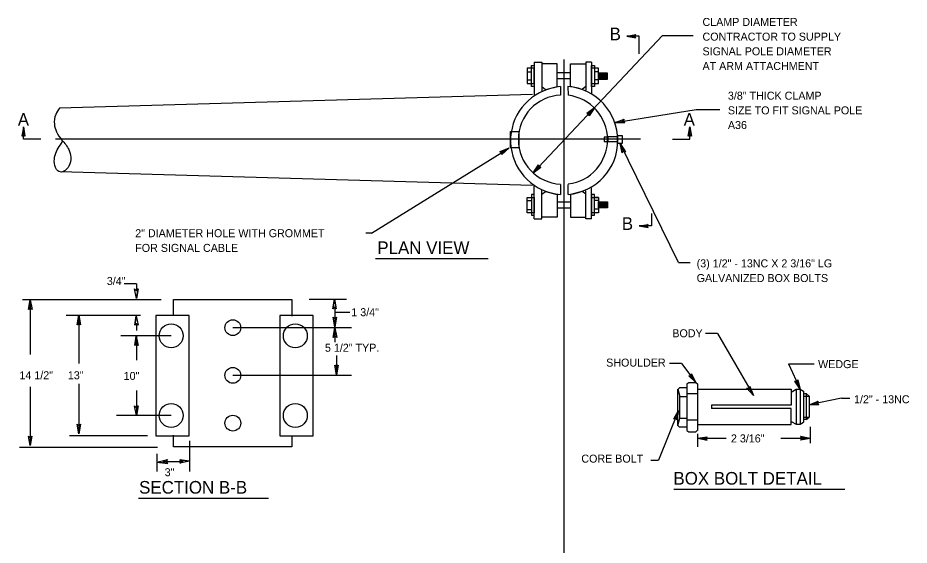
# Model space of a CAD drawing. Extents: x 104.4 to 111.7, y 116.1 to 126.1.
# Drawn here: x 104.4 to 111.45, y 121.98 to 126.14 of the extents above; entities that cross this region are included whole.
import ezdxf

# ---------------------------------------------------------------- set-up
doc = ezdxf.new("R2010")
doc.units = 0
for name, color, linetype in [('DETL-DIMS', 7, 'Continuous'), ('DETL-LINE', 7, 'Continuous'), ('DETL-NOTE', 7, 'Continuous'), ('DETL-TITL', 7, 'Continuous')]:
    doc.layers.add(name, color=color, linetype=linetype)

msp = doc.modelspace()

# ---------------------------------------------------------------- linework, layer by layer
at = {"layer": 'DETL-DIMS'}
for p, q in [((109.2139, 125.9989), (109.2854, 126.0115)), ((109.2719, 125.9989), (109.2854, 126.0115)), ((109.3114, 125.9989), (109.2139, 125.9989)), ((109.2139, 125.9989), (109.2854, 125.9863)), ((109.2854, 125.9863), (109.2719, 125.9989)), ((109.3114, 125.861), (109.3114, 125.9989)), ((108.7182, 120.2988), (108.7182, 125.8152)), ((104.4418, 125.282), (104.4292, 125.2105)), ((104.4418, 125.1845), (104.4418, 125.282)), ((104.4418, 125.282), (104.4544, 125.2105)), ((109.7109, 125.282), (109.6983, 125.2105)), ((109.7109, 125.1845), (109.7109, 125.282)), ((109.7109, 125.282), (109.7235, 125.2105)), ((104.4418, 125.224), (104.4292, 125.2105)), ((104.4544, 125.2105), (104.4418, 125.224)), ((104.5797, 125.1845), (104.4418, 125.1845)), ((109.3219, 125.1845), (104.6962, 125.1845)), ((109.573, 125.1845), (109.7109, 125.1845)), ((109.6983, 125.2105), (109.7109, 125.224)), ((109.7109, 125.224), (109.7235, 125.2105)), ((109.4076, 124.5995), (109.4076, 124.5002)), ((109.3101, 124.5002), (109.3816, 124.5128)), ((109.4076, 124.5002), (109.3101, 124.5002)), ((109.3101, 124.5002), (109.3816, 124.4876)), ((109.3681, 124.5002), (109.3816, 124.5128)), ((109.3816, 124.4876), (109.3681, 124.5002)), ((105.3352, 124.0425), (105.2386, 124.0425)), ((105.3352, 124.0425), (105.3352, 123.9883)), ((105.3353, 123.9271), (105.3218, 124.0025)), ((105.3352, 123.9883), (105.3218, 124.0025)), ((105.3484, 124.0025), (105.3352, 123.9883)), ((105.3353, 123.9271), (105.3484, 124.0025)), ((105.5311, 123.9169), (104.4348, 123.9169)), ((104.4967, 123.9157), (104.4837, 123.8403)), ((104.4967, 123.9157), (104.5103, 123.8403)), ((104.4968, 123.9152), (104.4968, 123.4847)), ((106.9973, 123.9197), (106.7012, 123.9197)), ((106.902, 123.9219), (106.889, 123.8464)), ((106.902, 123.9219), (106.9156, 123.8465)), ((104.4837, 123.8403), (104.4968, 123.8545)), ((104.4968, 123.8545), (104.5103, 123.8403)), ((106.889, 123.8464), (106.9021, 123.8607)), ((106.9021, 123.8607), (106.9156, 123.8465)), ((106.904, 123.8179), (107.0218, 123.8179)), ((106.9046, 123.8567), (106.9046, 123.717)), ((105.3672, 123.7914), (104.7807, 123.7914)), ((104.8794, 123.7951), (104.8664, 123.7196)), ((104.8794, 123.7951), (104.8929, 123.7196)), ((104.8794, 123.7945), (104.8794, 123.4124)), ((105.335, 123.7904), (105.322, 123.715)), ((105.335, 123.7904), (105.3486, 123.715)), ((106.9046, 123.7038), (106.8911, 123.7792)), ((106.9045, 123.765), (106.8911, 123.7792)), ((106.9176, 123.7793), (106.9045, 123.765)), ((106.9046, 123.7038), (106.9176, 123.7793)), ((104.8664, 123.7196), (104.8795, 123.7339)), ((104.8795, 123.7339), (104.8929, 123.7196)), ((105.322, 123.715), (105.3351, 123.7292)), ((105.3351, 123.7294), (105.3351, 123.6751)), ((105.3351, 123.7292), (105.3486, 123.715)), ((107.0374, 123.6962), (106.0983, 123.6962)), ((106.9056, 123.6945), (106.8925, 123.619)), ((106.9056, 123.6945), (106.9191, 123.6191)), ((106.9056, 123.6939), (106.9056, 123.5829)), ((105.6104, 123.6325), (105.2134, 123.6325)), ((105.335, 123.6305), (105.322, 123.5551)), ((105.335, 123.6305), (105.3486, 123.5551)), ((105.3351, 123.63), (105.3351, 123.439)), ((106.8925, 123.619), (106.9057, 123.6333)), ((106.9057, 123.6333), (106.9191, 123.6191)), ((109.9287, 123.6503), (109.8352, 123.6503)), ((109.9287, 123.6503), (110.2143, 123.1613)), ((105.322, 123.5551), (105.3351, 123.5694)), ((105.3351, 123.5694), (105.3486, 123.5551)), ((106.9166, 123.4772), (106.9166, 123.3375)), ((106.9166, 123.3243), (106.9031, 123.3997)), ((106.9165, 123.3855), (106.9031, 123.3997)), ((106.9297, 123.3997), (106.9165, 123.3855)), ((106.9166, 123.3243), (106.9297, 123.3997)), ((109.645, 123.4125), (109.5515, 123.4125)), ((109.645, 123.4125), (109.7577, 123.2628)), ((110.4922, 123.4107), (110.5829, 123.2093)), ((110.4922, 123.4107), (110.694, 123.4107)), ((109.7238, 123.3315), (109.7215, 123.3122)), ((109.7577, 123.2628), (109.7238, 123.3315)), ((107.0374, 123.3193), (106.0983, 123.3193)), ((109.7577, 123.2628), (109.7023, 123.3157)), ((109.7215, 123.3122), (109.7023, 123.3157)), ((110.5828, 123.2092), (110.5403, 123.273)), ((110.5582, 123.2653), (110.5403, 123.273)), ((110.5647, 123.2836), (110.5582, 123.2653)), ((110.5828, 123.2092), (110.5647, 123.2836)), ((104.4968, 123.2281), (104.4968, 122.7652)), ((104.8794, 123.2529), (104.8794, 122.8593)), ((105.3351, 123.1994), (105.3351, 123.0026)), ((110.2143, 123.1613), (110.1621, 123.2174)), ((110.181, 123.2127), (110.1621, 123.2174)), ((110.1844, 123.2318), (110.181, 123.2127)), ((110.2143, 123.1613), (110.1844, 123.2318)), ((110.6538, 123.0873), (110.7251, 123.1152)), ((110.9091, 123.1389), (110.6558, 123.0873)), ((110.7138, 123.0993), (110.7251, 123.1152)), ((110.9091, 123.1389), (110.9761, 123.1389)), ((105.3353, 123.0021), (105.3218, 123.0775)), ((105.3352, 123.0633), (105.3218, 123.0775)), ((105.3484, 123.0776), (105.3352, 123.0633)), ((105.3353, 123.0021), (105.3484, 123.0776)), ((109.6226, 123.0425), (109.4634, 122.65)), ((109.6226, 123.0425), (109.5844, 122.9761)), ((109.6226, 123.0425), (109.5844, 122.9761)), ((109.6226, 123.0425), (109.6094, 122.967)), ((109.6226, 123.0425), (109.6094, 122.967)), ((110.6538, 123.0873), (110.7303, 123.0891)), ((110.7303, 123.0891), (110.7138, 123.0993)), ((105.6104, 123.0026), (105.1777, 123.0026)), ((109.5844, 122.9761), (109.6017, 122.985)), ((109.5844, 122.9761), (109.6017, 122.985)), ((109.6017, 122.985), (109.6094, 122.967)), ((109.6017, 122.985), (109.6094, 122.967)), ((104.8797, 122.8588), (104.8662, 122.9342)), ((104.8796, 122.92), (104.8662, 122.9342)), ((104.8927, 122.9343), (104.8796, 122.92)), ((104.8797, 122.8588), (104.8927, 122.9343)), ((110.6624, 122.9124), (110.6624, 122.7825)), ((104.497, 122.7648), (104.4835, 122.8402)), ((104.4969, 122.8259), (104.4835, 122.8402)), ((104.5101, 122.8402), (104.4969, 122.8259)), ((104.497, 122.7648), (104.5101, 122.8402)), ((105.4225, 122.8426), (104.8079, 122.8426)), ((109.7723, 122.8569), (109.7723, 122.7547)), ((109.7732, 122.822), (109.8486, 122.835)), ((109.8343, 122.8217), (109.8486, 122.835)), ((110.6624, 122.8219), (110.5871, 122.8353)), ((110.5871, 122.8353), (110.6013, 122.822)), ((105.7556, 122.8029), (105.7556, 122.5588)), ((109.7732, 122.822), (109.8485, 122.8083)), ((109.9975, 122.8219), (109.7737, 122.8219)), ((109.8485, 122.8083), (109.8343, 122.8217)), ((110.6624, 122.8219), (110.4303, 122.8219)), ((110.6013, 122.822), (110.587, 122.8087)), ((110.6624, 122.8219), (110.587, 122.8087)), ((104.4106, 122.7516), (105.5024, 122.7516)), ((105.496, 122.6985), (105.496, 122.5588)), ((105.4976, 122.6344), (105.5825, 122.6541)), ((105.4976, 122.6344), (105.584, 122.6239)), ((105.5456, 122.6382), (105.7064, 122.6382)), ((105.5671, 122.6381), (105.5825, 122.6541)), ((105.584, 122.6239), (105.5671, 122.6381)), ((105.7548, 122.6425), (105.6788, 122.6517)), ((105.6788, 122.6517), (105.6937, 122.6393)), ((105.7548, 122.6425), (105.6802, 122.6252)), ((105.6937, 122.6393), (105.6802, 122.6252)), ((109.4027, 122.6494), (109.4646, 122.6494))]:
    msp.add_line(p, q, dxfattribs=at)
for points in [[(109.2854, 125.9863), (109.2139, 125.9989), (109.2854, 126.0115), (109.2719, 125.9989)], [(104.4544, 125.2105), (104.4418, 125.282), (104.4292, 125.2105), (104.4418, 125.224)], [(109.6983, 125.2105), (109.7109, 125.282), (109.7235, 125.2105), (109.7109, 125.224)], [(109.3816, 124.4876), (109.3101, 124.5002), (109.3816, 124.5128), (109.3681, 124.5002)], [(105.3484, 124.0025), (105.3353, 123.9271), (105.3218, 124.0025), (105.3352, 123.9883)], [(104.4837, 123.8403), (104.4967, 123.9157), (104.5103, 123.8403), (104.4968, 123.8545)], [(106.889, 123.8464), (106.902, 123.9219), (106.9156, 123.8465), (106.9021, 123.8607)], [(104.8664, 123.7196), (104.8794, 123.7951), (104.8929, 123.7196), (104.8795, 123.7339)], [(105.322, 123.715), (105.335, 123.7904), (105.3486, 123.715), (105.3351, 123.7292)], [(106.9176, 123.7793), (106.9046, 123.7038), (106.8911, 123.7792), (106.9045, 123.765)], [(106.8925, 123.619), (106.9056, 123.6945), (106.9191, 123.6191), (106.9057, 123.6333)], [(105.322, 123.5551), (105.335, 123.6305), (105.3486, 123.5551), (105.3351, 123.5694)], [(106.9297, 123.3997), (106.9166, 123.3243), (106.9031, 123.3997), (106.9165, 123.3855)], [(109.7238, 123.3315), (109.7577, 123.2628), (109.7023, 123.3157), (109.7215, 123.3122)], [(110.5647, 123.2836), (110.5828, 123.2092), (110.5403, 123.273), (110.5582, 123.2653)], [(110.1844, 123.2318), (110.2143, 123.1613), (110.1621, 123.2174), (110.181, 123.2127)], [(110.7303, 123.0891), (110.6538, 123.0873), (110.7251, 123.1152), (110.7138, 123.0993)], [(105.3484, 123.0776), (105.3353, 123.0021), (105.3218, 123.0775), (105.3352, 123.0633)], [(109.5844, 122.9761), (109.6226, 123.0425), (109.6094, 122.967), (109.6017, 122.985)], [(109.5844, 122.9761), (109.6226, 123.0425), (109.6094, 122.967), (109.6017, 122.985)], [(104.8927, 122.9343), (104.8797, 122.8588), (104.8662, 122.9342), (104.8796, 122.92)], [(104.5101, 122.8402), (104.497, 122.7648), (104.4835, 122.8402), (104.4969, 122.8259)], [(109.8485, 122.8083), (109.7732, 122.822), (109.8486, 122.835), (109.8343, 122.8217)], [(110.5871, 122.8353), (110.6624, 122.8219), (110.587, 122.8087), (110.6013, 122.822)], [(105.584, 122.6239), (105.4976, 122.6344), (105.5825, 122.6541), (105.5671, 122.6381)], [(105.6788, 122.6517), (105.7548, 122.6425), (105.6802, 122.6252), (105.6937, 122.6393)]]:
    msp.add_lwpolyline(points, close=True, dxfattribs=at)
at = {"layer": 'DETL-LINE'}
for p, q in [((108.4805, 125.7941), (108.4805, 125.5783)), ((108.4805, 125.7941), (108.5397, 125.7941)), ((108.5397, 125.7941), (108.5397, 125.5638)), ((108.9339, 125.7941), (108.8893, 125.7941)), ((108.8893, 125.7941), (108.8893, 125.573)), ((108.9339, 125.7941), (108.9339, 125.5783)), ((108.6615, 125.7811), (108.5424, 125.7811)), ((108.6615, 125.6022), (108.6615, 125.7811)), ((108.7675, 125.6022), (108.7675, 125.7811)), ((108.7675, 125.7811), (108.8866, 125.7811)), ((108.4251, 125.7185), (108.4566, 125.7185)), ((108.4251, 125.654), (108.4566, 125.654)), ((108.7675, 125.6631), (108.6629, 125.6631)), ((108.7688, 125.7108), (108.6642, 125.7108)), ((108.9979, 125.7078), (108.9979, 125.6607)), ((109.0067, 125.7078), (109.0067, 125.6607)), ((109.0155, 125.7078), (109.0155, 125.6607)), ((109.0243, 125.7078), (109.0243, 125.6607)), ((109.0331, 125.7078), (109.0331, 125.6607)), ((109.0419, 125.7078), (109.0419, 125.6607)), ((109.0506, 125.7078), (109.0506, 125.6607)), ((108.5397, 125.6009), (108.5688, 125.5783)), ((108.5688, 125.5783), (108.6615, 125.6022)), ((108.688, 125.6022), (108.6898, 125.5343)), ((108.7476, 125.6022), (108.7487, 125.5324)), ((108.8602, 125.5783), (108.7675, 125.6022)), ((108.8893, 125.6009), (108.8602, 125.5783)), ((108.4675, 125.5378), (104.7279, 125.4314)), ((108.4805, 125.5783), (108.4805, 125.5346)), ((108.9339, 125.5783), (108.9339, 125.5505)), ((108.4675, 124.8204), (104.7325, 124.9266)), ((108.4805, 124.7731), (108.4805, 124.8168)), ((108.688, 124.8287), (108.688, 124.7492)), ((108.7476, 124.8287), (108.7476, 124.7492)), ((108.4805, 124.5573), (108.4805, 124.7731)), ((108.5397, 124.5573), (108.5397, 124.7876)), ((108.5397, 124.7505), (108.5688, 124.7731)), ((108.5688, 124.7731), (108.6615, 124.7492)), ((108.6615, 124.7492), (108.6615, 124.5703)), ((108.8602, 124.7731), (108.7675, 124.7492)), ((108.7675, 124.7492), (108.7675, 124.5703)), ((108.8893, 124.7505), (108.8602, 124.7731)), ((108.8893, 124.5573), (108.8893, 124.7784)), ((108.9339, 124.7731), (108.9339, 124.8009)), ((108.9339, 124.5573), (108.9339, 124.7731)), ((108.4249, 124.7005), (108.4592, 124.7005)), ((108.7675, 124.6883), (108.6629, 124.6883)), ((108.9888, 124.726), (108.9566, 124.726)), ((108.9888, 124.7005), (108.9566, 124.7005)), ((108.9979, 124.6907), (108.9979, 124.6436)), ((109.0067, 124.6907), (109.0067, 124.6436)), ((109.0155, 124.6907), (109.0155, 124.6436)), ((109.0243, 124.6907), (109.0243, 124.6436)), ((109.0331, 124.6907), (109.0331, 124.6436)), ((109.0419, 124.6907), (109.0419, 124.6436)), ((109.0506, 124.6907), (109.0506, 124.6436)), ((109.0594, 124.6907), (109.0594, 124.6436)), ((108.4249, 124.6305), (108.4592, 124.6305)), ((108.7688, 124.6406), (108.6642, 124.6406)), ((108.9888, 124.6329), (108.9566, 124.6329)), ((108.4805, 124.5573), (108.5397, 124.5573)), ((108.6615, 124.5703), (108.5424, 124.5703)), ((108.7675, 124.5703), (108.8866, 124.5703)), ((108.9339, 124.5573), (108.8893, 124.5573)), ((109.6862, 123.2517), (109.7037, 123.2628)), ((109.7037, 123.2628), (109.7577, 123.2628)), ((109.7577, 123.2628), (109.7718, 123.2517)), ((109.6307, 123.2205), (109.6161, 123.2088)), ((109.6161, 122.9226), (109.6161, 123.2103)), ((109.6161, 123.2103), (109.6322, 123.1519)), ((109.6847, 123.2205), (109.6307, 123.2205)), ((109.6862, 123.2517), (109.6862, 122.8846)), ((109.7718, 123.2517), (109.7718, 122.8846)), ((109.7759, 123.2096), (110.5123, 123.2096)), ((110.5123, 123.2096), (110.5123, 123.0838)), ((110.513, 123.188), (110.553, 123.2093)), ((110.553, 123.2093), (110.5829, 123.2093)), ((110.553, 123.2093), (110.553, 122.9346)), ((110.5829, 123.2093), (110.6091, 123.1943)), ((110.5829, 123.2093), (110.5829, 122.9346)), ((110.6091, 123.1943), (110.6091, 122.9495)), ((109.6322, 123.1519), (109.6833, 123.1519)), ((109.6322, 122.9825), (109.6322, 123.1519)), ((109.6862, 123.1752), (109.7693, 123.1752)), ((110.6104, 123.1755), (110.6303, 123.1755)), ((110.6104, 123.1543), (110.654, 123.1543)), ((110.6303, 123.1755), (110.6303, 122.9708)), ((110.6303, 123.1755), (110.654, 123.1543)), ((110.654, 123.1543), (110.654, 122.9883)), ((110.5123, 123.0838), (109.8837, 123.0838)), ((109.8837, 123.0838), (109.8837, 123.0838)), ((109.8837, 123.0838), (109.8837, 123.0838)), ((109.8837, 123.0838), (109.8837, 123.0569)), ((110.5123, 123.0569), (109.8837, 123.0569)), ((110.5123, 122.9321), (110.5123, 123.0579)), ((109.6161, 122.9226), (109.6322, 122.9825)), ((109.6322, 122.9825), (109.6833, 122.9825)), ((110.6104, 122.9883), (110.654, 122.9883)), ((110.6303, 122.9708), (110.654, 122.9883)), ((109.6307, 122.911), (109.6161, 122.9226)), ((109.6847, 122.911), (109.6307, 122.911)), ((109.6862, 122.9679), (109.7693, 122.9679)), ((109.7759, 122.9321), (110.5123, 122.9321)), ((110.513, 122.9558), (110.553, 122.9346)), ((110.553, 122.9346), (110.5829, 122.9346)), ((110.5829, 122.9346), (110.6091, 122.9495)), ((110.6303, 122.9708), (110.6104, 122.9708)), ((109.6862, 122.8846), (109.7037, 122.8745)), ((109.7037, 122.8745), (109.7577, 122.8745)), ((109.7577, 122.8745), (109.7718, 122.8856))]:
    msp.add_line(p, q, dxfattribs=at)
for points in [[(108.4249, 125.6254), (108.4798, 125.6254), (108.4798, 125.747), (108.4249, 125.747)], [(108.4812, 125.6027), (108.4591, 125.6027), (108.4591, 125.7674), (108.4812, 125.7674)], [(108.9339, 125.6254), (108.9888, 125.6254), (108.9888, 125.747), (108.9339, 125.747)], [(108.9565, 125.6027), (108.9345, 125.6027), (108.9345, 125.7674), (108.9565, 125.7674)], [(108.9888, 125.6607), (109.0594, 125.6607), (109.0594, 125.7078), (108.9888, 125.7078)], [(108.2928, 125.2464), (108.3583, 125.2464), (108.3583, 125.1185), (108.2928, 125.1185)], [(109.0662, 125.2008), (109.0329, 125.2008), (109.0329, 125.1674), (109.0662, 125.1674)], [(109.0628, 125.2067), (109.1358, 125.2067), (109.1358, 125.1636), (109.0628, 125.1636)], [(109.1395, 125.2142), (109.177, 125.2142), (109.177, 125.1505), (109.1395, 125.1505)], [(109.1414, 125.2142), (109.177, 125.2142), (109.177, 125.1505), (109.1414, 125.1505)], [(108.4812, 124.7486), (108.4591, 124.7486), (108.4591, 124.584), (108.4812, 124.584)], [(108.9565, 124.7486), (108.9345, 124.7486), (108.9345, 124.584), (108.9565, 124.584)], [(108.4249, 124.726), (108.4798, 124.726), (108.4798, 124.6044), (108.4249, 124.6044)], [(108.9339, 124.726), (108.9888, 124.726), (108.9888, 124.6044), (108.9339, 124.6044)], [(108.9888, 124.6907), (109.0594, 124.6907), (109.0594, 124.6436), (108.9888, 124.6436)], [(105.7518, 123.7928), (105.4889, 123.7928), (105.4889, 122.8407), (105.7518, 122.8407)], [(106.7334, 123.7928), (106.4705, 123.7928), (106.4705, 122.8407), (106.7334, 122.8407)]]:
    msp.add_lwpolyline(points, close=True, dxfattribs=at)
for points in [[(108.9888, 125.747), (108.9888, 125.747), (108.9566, 125.747)], [(108.9888, 125.7173), (108.9566, 125.7173)], [(108.9888, 125.6536), (108.9566, 125.6536)], [(105.6294, 123.7953), (105.6294, 123.9197), (106.5632, 123.9197), (106.5632, 123.787)], [(106.5632, 122.8421), (106.5632, 122.7539), (105.6294, 122.7539), (105.6294, 122.8466)]]:
    msp.add_lwpolyline(points, dxfattribs=at)
for centre, radius in [((106.0983, 123.6962), 0.0625), ((105.6104, 123.6325), 0.0947), ((106.592, 123.6325), 0.0947), ((106.0983, 123.3193), 0.0625), ((105.6104, 123.0026), 0.0947), ((106.592, 123.0026), 0.0947), ((106.0983, 122.9423), 0.0625)]:
    msp.add_circle(centre, radius, dxfattribs=at)
for centre, radius, start, end in [((108.7205, 125.1745), 0.4267, 107.53481, 265.6591), ((108.7585, 125.0775), 0.5294, 97.65443, 112.87918), ((108.7136, 125.1754), 0.4281, 274.89789, 85.44885), ((108.7079, 125.1821), 0.3527, 92.93898, 266.76591), ((108.7079, 125.1821), 0.3527, 276.85711, 83.35442)]:
    msp.add_arc(centre, radius, start, end, dxfattribs=at)
msp.add_spline([(104.7279, 125.4314), (104.6981, 125.3802), (104.6872, 125.3041), (104.7035, 125.2443), (104.747, 125.1791), (104.8013, 125.103), (104.8176, 125.0432), (104.8013, 124.9726), (104.7325, 124.9266), (104.7144, 124.9345), (104.6872, 124.9943), (104.6927, 125.0595), (104.7524, 125.1682)], degree=3, dxfattribs=at)
at = {"layer": 'DETL-NOTE'}
for p, q in [((108.4723, 124.9199), (109.4962, 126.0062)), ((109.4962, 126.0062), (109.7363, 126.0062)), ((108.9579, 125.4336), (108.8965, 125.3879)), ((108.8965, 125.3879), (108.9159, 125.3891)), ((108.9579, 125.4336), (108.9158, 125.3696)), ((108.9159, 125.3891), (108.9158, 125.3696)), ((109.1197, 125.3186), (109.7605, 125.4204)), ((109.7605, 125.4204), (109.9475, 125.4204)), ((109.1197, 125.3186), (109.1922, 125.3432)), ((109.1197, 125.3186), (109.1962, 125.3169)), ((109.1802, 125.3279), (109.1922, 125.3432)), ((109.1962, 125.3169), (109.1802, 125.3279)), ((107.1943, 124.4419), (108.2799, 125.116)), ((108.2799, 125.116), (108.2093, 125.0864)), ((108.2093, 125.0864), (108.2284, 125.0829)), ((108.2799, 125.116), (108.2237, 125.064)), ((109.6225, 124.2106), (109.1603, 125.1527)), ((109.1609, 125.1519), (109.1765, 125.0769)), ((109.1609, 125.1519), (109.2013, 125.0868)), ((109.1765, 125.0769), (109.1836, 125.0951)), ((109.1836, 125.0951), (109.2013, 125.0868)), ((108.2284, 125.0829), (108.2237, 125.064)), ((108.4721, 124.9199), (108.5142, 124.9839)), ((108.4721, 124.9199), (108.5336, 124.9656)), ((108.5141, 124.9644), (108.5142, 124.9839)), ((108.5336, 124.9656), (108.5141, 124.9644)), ((107.1943, 124.4419), (107.1497, 124.4419)), ((109.6225, 124.2106), (109.7141, 124.2106))]:
    msp.add_line(p, q, dxfattribs=at)
for points in [[(108.8965, 125.3879), (108.9579, 125.4336), (108.9158, 125.3696), (108.9159, 125.3891)], [(109.1962, 125.3169), (109.1197, 125.3186), (109.1922, 125.3432), (109.1802, 125.3279)], [(108.2093, 125.0864), (108.2799, 125.116), (108.2237, 125.064), (108.2284, 125.0829)], [(109.1765, 125.0769), (109.1609, 125.1519), (109.2013, 125.0868), (109.1836, 125.0951)], [(108.5336, 124.9656), (108.4721, 124.9199), (108.5142, 124.9839), (108.5141, 124.9644)]]:
    msp.add_lwpolyline(points, close=True, dxfattribs=at)
at = {"layer": 'DETL-TITL'}
for p, q in [((107.2255, 124.2417), (108.1154, 124.2417)), ((109.5839, 122.4199), (110.9355, 122.4199)), ((105.3509, 122.3488), (106.3805, 122.3488))]:
    msp.add_line(p, q, dxfattribs=at)

# ---------------------------------------------------------------- texts
at = {"layer": 'DETL-DIMS'}
for s, height, p in [('3/4"', 0.06328, (105.1019, 124.0333)), ('1 3/4"', 0.06328, (107.0349, 123.787)), ('5 1/2" TYP.', 0.063281, (106.8265, 123.5062)), ('14 1/2"', 0.06328, (104.4109, 123.2887)), ('13"', 0.06328, (104.7936, 123.2887)), ('10"', 0.06328, (105.2349, 123.2834)), ('2 3/16"', 0.06328, (110.0361, 122.7897)), ('3"', 0.06328, (105.5591, 122.5225))]:
    msp.add_text(s, height=height, rotation=360, dxfattribs=at).set_placement(p)
at = {"layer": 'DETL-NOTE'}
for s, height, p in [('CLAMP DIAMETER', 0.063281, (109.8113, 126.0802)), ('CONTRACTOR TO SUPPLY', 0.063281, (109.8113, 125.9642)), ('SIGNAL POLE DIAMETER ', 0.063281, (109.8113, 125.8482)), ('AT ARM ATTACHMENT', 0.063281, (109.8113, 125.7322)), ('3/8" THICK CLAMP', 0.063281, (110.0121, 125.4977)), ('SIZE TO FIT SIGNAL POLE', 0.063281, (110.0121, 125.3817)), ('A36', 0.06328, (110.0121, 125.2657)), ('2" DIAMETER HOLE WITH GROMMET', 0.063281, (105.3264, 124.4111)), ('FOR SIGNAL CABLE', 0.063281, (105.3264, 124.295)), ('(3) 1/2" - 13NC X 2 3/16" LG', 0.063281, (109.7651, 124.1727)), ('GALVANIZED BOX BOLTS', 0.063281, (109.7651, 124.0567)), ('BODY', 0.06328, (109.5726, 123.6205)), ('SHOULDER', 0.06328, (109.0497, 123.3887)), ('WEDGE', 0.06328, (110.7251, 123.3767)), ('1/2" - 13NC', 0.063281, (111.0092, 123.099)), ('CORE BOLT', 0.06328, (108.8534, 122.63))]:
    msp.add_text(s, height=height, rotation=360, dxfattribs=at).set_placement(p)
at = {"layer": 'DETL-TITL'}
for s, p in [('B', (109.0771, 125.9672)), ('A', (104.3979, 125.2915)), ('A', (109.6622, 125.2915)), ('B', (109.1732, 124.4685)), ('PLAN VIEW', (107.2402, 124.2779)), ('BOX BOLT DETAIL', (109.5814, 122.456)), ('SECTION B-B', (105.3567, 122.3849))]:
    msp.add_text(s, height=0.1, dxfattribs=at).set_placement(p)

doc.saveas('drawing.dxf')
